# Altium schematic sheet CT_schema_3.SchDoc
size 276 x 169 mm
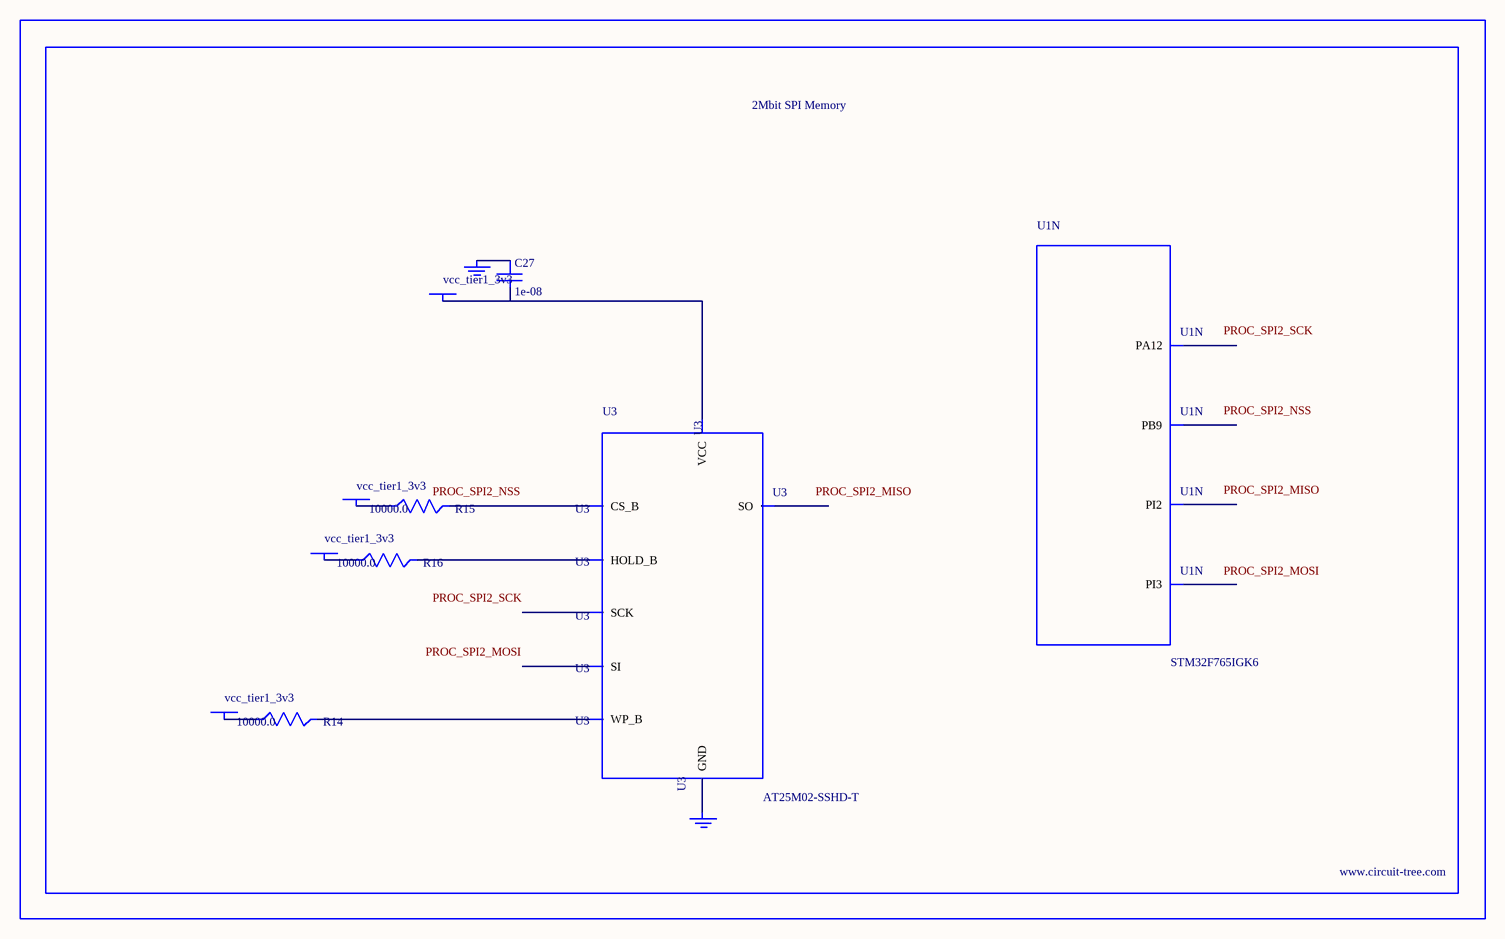
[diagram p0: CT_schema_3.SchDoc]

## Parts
BORDER2  (no value)
C27  1e-08  [C0402]
GND_INSTANCE_2_0  (no value)
GND_INSTANCE_2_1  (no value)
POWER_INSTANCE_2_0  vcc_tier1_3v3
POWER_INSTANCE_2_1  vcc_tier1_3v3
POWER_INSTANCE_2_2  vcc_tier1_3v3
POWER_INSTANCE_2_3  vcc_tier1_3v3
R14  10000.0  [R0603]
R15  10000.0  [R0603]
R16  10000.0  [R0603]
U1  STM32F765IGK6  [UFBGA176_25]  (part N of 17)
U3  AT25M02-SSHD-T  [SOIC-8]

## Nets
NetC27_1: C27.1 GND_INSTANCE_2_0.0(GND)
NetC27_2: C27.2 POWER_INSTANCE_2_3.0(PWR) U3.8(VCC)
NetGND_INSTANCE_2_1_0: GND_INSTANCE_2_1.0(GND) U3.4(GND)
NetPOWER_INSTANCE_2_0_0: POWER_INSTANCE_2_0.0(PWR) R15.1
NetPOWER_INSTANCE_2_1_0: POWER_INSTANCE_2_1.0(PWR) R14.1
NetPOWER_INSTANCE_2_2_0: POWER_INSTANCE_2_2.0(PWR) R16.1
NetR14_2: R14.2 U3.3(WP_B)
NetR15_2: R15.2 U3.1(CS_B)
NetR16_2: R16.2 U3.7(HOLD_B)

Not connected (* = marked no-connect by the designer): U1 B4(PB9) B15(PA12) C13(PI3) C14(PI2); U3 2(SO) 5(SI) 6(SCK)

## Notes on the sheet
- Labels drawn without touching a wire or pin: PROC_SPI2_MISO, PROC_SPI2_MOSI, PROC_SPI2_NSS, PROC_SPI2_SCK

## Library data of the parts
BORDER2 = BORDER_PAGE2
C27 = C0402C103K3RAC
GND_INSTANCE_2_0 GND_INSTANCE_2_1 = GND
POWER_INSTANCE_2_0-POWER_INSTANCE_2_3 = PWR
R14-R16 = RC0603JR-0710KL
